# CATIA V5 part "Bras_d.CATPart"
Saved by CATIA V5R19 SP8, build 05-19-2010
Part number: Bras_d
Bounding box of the stored display mesh (mm): x -50 to 50, y -224.818 to 50, z -250 to 30
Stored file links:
  G:\EU_thinkMotion\CFAO_2010\MMS_groupe1\MMS_groupe1\OK\vduret\vduret\CATIA\Bras_d.CATPart
  G:\EU_thinkMotion\CFAO_2010\MMS_groupe1\MMS_groupe1\OK\vduret\vduret\CATIA\Axe_outil_g.CATPart
  G:\EU_thinkMotion\CFAO_2010\MMS_groupe1\MMS_groupe1\OK\vduret\vduret\CATIA\Axe.CATPart
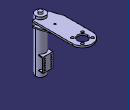
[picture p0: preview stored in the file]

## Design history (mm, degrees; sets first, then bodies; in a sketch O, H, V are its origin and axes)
Parameters
  Longueur_axe = 0 mm
External parameters (linked from other documents)
  External.Hauteur_bras = 200 mm
  External.Longueur_axe_couronne = 200 mm
Body1 (main body)
  Sketch1 on xy-plane, origin (0, 0, 0), H (1, 0, 0), V (0, 1, 0)
    arc A1 centre (0, 0) radius 50 from (50, 0) to (-50, 0) ccw
    point P1 (-50, 0)
    line L1 (-50, 0) -> (-50, -140)
    arc A2 centre (10, -200) radius 25 from (35, -200) to (-15, -200) ccw
    point P3 (10, -200)
    point P4 (50, 0)
    point P6 (35, -200)
    construction line L2 (-167.2305, -200) -> (322.7695, -200)
    circle A3 centre (0, 0) radius 25
    construction line L3 (-120, 0) -> (240, 0)
    point P9 (-120, 0)
    construction line L4 (0, -80) -> (0, 120)
    point P11 (0, -80)
    circle A4 centre (-25, 25) radius 7
    point P13 (-25, 25)
    circle A5 centre (25, 25) radius 7
    circle A6 centre (-25, -25) radius 7
    circle A7 centre (25, -25) radius 7
    line L5 (50, 0) -> (50, -200)
    point P17 (50, -200)
    line L6 (-50, -140) -> (-30, -200)
    point P18 (-30, -200)
    line L7 (-30, -200) -> (-15, -200)
    line L8 (35, -200) -> (50, -200)
    circle A8 centre (10, -127.5) radius 5
    point P20 (10, -127.5)
    axis line L9 (10, -200) -> (10, -128.2614)
    radius A1 = 50
    radius A2 = 25
    distance P3 H = 200 {= External.Hauteur_bras}
    length L1 = 140
    radius A3 = 25
    radius A4 = 7
    distance P13 L3 = 25
    distance P13 L4 = 25
    distance P3 L5 = 40
    length L7 = 15
    length L8 = 15
    radius A8 = 5
    distance P20 L2 = 72.5
    coincidence: P1 H, P4 H, P6 L2, P9 H, P11 V, P18 L2, P17 L8, P3 L2, P20 L9
    tangency: L1 A1, L5 A1
    horizontal: L2 H, L3 H, L7 H, L8 H
    vertical: L4 V, L9 V
    symmetry: A4 A5 L4, A4 A6 L3, A5 A7 L3
  Pad1: profile Sketch1, direction (0, 0, 1), length 8
  Plane1: type Offset, RefPlane xy-plane, Offset 18, reversed
  Sketch2 on Plane1, origin (0, 0, -18), H (1, 0, 0), V (0, 1, 0)
    arc A1 centre (10, -200) radius 25 from (35, -200) to (-15, -200) ccw
    reference projected arc E1 centre (10, -200) radius 25 from (35, -200) to (-15, -200) ccw from edge [face of Pad1 from Sketch1.A2 | end face of Pad1]
    line L1 (-15, -200) -> (-30, -200)
    point P3 (-30, -200)
    arc A2 centre (10, -127.5) radius 16 from (25.2387, -122.6235) to (-5.2387, -122.6235) ccw
    reference projected circle E2 centre (10, -127.5) radius 5 from edge [end face of Pad1 | face of Pad1 from Sketch1.A8]
    reference projected line E3 (-30, -200) -> (-15, -200) from edge [face of Pad1 from Sketch1.L7 | end face of Pad1]
    reference projected line E4 (-50, -140) -> (-30, -200) from edge [face of Pad1 from Sketch1.L6 | end face of Pad1]
    line L2 (35, -200) -> (50, -200)
    point P5 (35, -200)
    point P6 (50, -200)
    reference projected line E5 (35, -200) -> (50, -200) from edge [face of Pad1 from Sketch1.L8 | end face of Pad1]
    reference projected line E6 (50, -200) -> (50, 0) from edge [face of Pad1 from Sketch1.L5 | end face of Pad1]
    line L3 (50, -200) -> (25.2387, -122.6235)
    line L4 (-30, -200) -> (-5.2387, -122.6235)
    circle A3 centre (10, -127.5) radius 5
    reference projected circle E7 centre (10, -127.5) radius 5 from edge [end face of Pad1 | face of Pad1 from Sketch1.A8]
    reference projected circle E8 centre (10, -127.5) radius 5 from edge [end face of Pad1 | face of Pad1 from Sketch1.A8]
    radius A2 = 16
    coincidence: A1 E1, P3 E3, P3 E4, P5 L1, L2 E5, P6 E6, A3 E7
    horizontal: L1 H
    concentricity: A2 E2, A3 E8
    tangency: L3 A2, L4 A2
  Pad2: profile Sketch2, direction (0, 0, -1), length 6
  Sketch3 on xy-plane, origin (0, 0, 0), H (1, 0, 0), V (0, 1, 0)
    circle A1 centre (10, -200) radius 25
    reference projected arc E1 centre (10, -200) radius 25 from (35, -200) to (-15, -200) ccw from edge [face of Pad1 from Sketch1.A2 | end face of Pad1]
    coincidence: A1 E1
  Pad3: profile Sketch3, direction (0, 0, 1), length 20, opposite side length 240 {= External.Longueur_axe_couronne +40mm}
  Sketch4 on start face of Pad3, origin (0, 0, -240), H (1, 0, 0), V (0, -1, 0)
    circle A1 centre (10, 200) radius 10
    reference projected circle E1 centre (10, 200) radius 25 from edge [start face of Pad3 | face of Pad3 from Sketch3.A1]
    radius A1 = 10
    concentricity: A1 E1
  Pad4: profile Sketch4, direction (0, 0, -1), length 10
  Sketch5 on end face of Pad3, origin (0, 0, 20), H (1, 0, 0), V (0, 1, 0)
    circle A1 centre (10, -200) radius 10
    reference projected circle E1 centre (10, -200) radius 25 from edge [face of Pad3 from Sketch3.A1 | end face of Pad3]
    radius A1 = 10
    concentricity: A1 E1
  Pad5: profile Sketch5, direction (0, 0, 1), length 10
  Point1: type Center, Curve edge [start face of Pad3 | face of Pad3 from Sketch3.A1]
  Plane2: type OffsetPt, RefPlane yz-plane, RefPoint Point1
  Sketch6 on Plane2, origin (10, 0, 0), H (0, 1, 0), V (0, 0, 1)
    line L1 (-184, -140) -> (-162, -140)
    line L2 (-162, -140) -> (-162, -210)
    line L3 (-162, -210) -> (-184, -210)
    line L4 (-184, -210) -> (-184, -206)
    line L5 (-184, -206) -> (-166, -206)
    line L6 (-166, -206) -> (-166, -144)
    line L7 (-166, -144) -> (-184, -144)
    line L8 (-184, -144) -> (-184, -140)
    reference projected line E1 through (-200, 0) direction (0, 1) from axis of face of Pad3 from Sketch3.A1
    reference projected line E2 (-225, -240) -> (-175, -240) from edge [start face of Pad3 | face of Pad3 from Sketch3.A1]
    length L2 = 70
    distance L1 L7 = 4
    distance L5 L3 = 4
    distance L6 L2 = 4
    distance L8 E1 = 16
    length L1 = 22
    distance L3 E2 = 30
    horizontal: L1 H, L3 H, L5 H, L7 H
    vertical: L2 V, L4 V, L6 V, L8 V
    coincidence: L4 L8
  Pad6: profile Sketch6, direction (1, 0, 0), length 25, mirrored extent
  Sketch7 on face of Pad6 from Sketch6.L2, origin (0, -162, 0), H (-1, 0, 0), V (0, 0, 1)
    circle A1 centre (-26, -170) radius 3
    point P1 (-26, -170)
    construction line L1 (65, -380) -> (65, -460)
    circle A2 centre (-22.801, -391.0745) radius 0
    point P5 (-26, -150)
    circle A3 centre (-26, -150) radius 3
    point P6 (-27, -430)
    point P7 (-26, -160)
    circle A4 centre (-26, -160) radius 3
    construction line L2 (-26, -460) -> (-26, -370)
    reference projected line E1 (-35, -450) -> (-35, -380) from edge [face of Pad6 from Sketch6.L2 | end face of Pad6]
    reference projected line E2 (15, -450) -> (15, -380) from edge [start face of Pad6 | face of Pad6 from Sketch6.L2]
    construction line L3 (-10, -460) -> (-10, -380)
    reference projected line E3 (-35, -450) -> (-35, -380) from edge [face of Pad6 from Sketch6.L2 | end face of Pad6]
    axis line L4 (-51.764, -175) -> (28.236, -175)
    reference projected line E4 (15, -140) -> (-35, -140) from edge [face of Pad6 from Sketch6.L1 | face of Pad6 from Sketch6.L2]
    reference projected line E5 (15, -140) -> (-35, -140) from edge [face of Pad6 from Sketch6.L1 | face of Pad6 from Sketch6.L2]
    circle A5 centre (-26, -200) radius 3
    circle A6 centre (-26, -190) radius 3
    circle A7 centre (-26, -180) radius 3
    circle A8 centre (6, -150) radius 3
    circle A9 centre (6, -160) radius 3
    circle A10 centre (6, -170) radius 3
    circle A11 centre (6, -180) radius 3
    circle A12 centre (6, -190) radius 3
    circle A13 centre (6, -200) radius 3
    radius A1 = 3
    distance P5 P7 = 10
    distance P7 P1 = 10
    distance L3 E3 = 25
    distance L4 E4 = 35
    radius A3 = 3
    radius A4 = 3
    radius A1 = 3 (reference)
    distance P5 E5 = 10
    distance L2 L3 = 16
    vertical: L1 V, L2 V, L3 V
    coincidence: L2 P5, P7 L2, P1 L2
    symmetry: L1 E1 E2, A3 A5 L4, A4 A6 L4, A1 A7 L4, A3 A8 L3, A4 A9 L3, A1 A10 L3, A7 A11 L3, A6 A12 L3, A5 A13 L3
    horizontal: L4 H
  Pocket1: profile Sketch7, direction (0, -1, 0), through (limit type 6)
  Sketch8 on start face of Pad1, origin (0, 0, 0), H (1, 0, 0), V (0, -1, 0)
    circle A1 centre (10, 127.5) radius 5
    reference projected circle E1 centre (10, 127.5) radius 5 from edge [face of Pad1 from Sketch1.A8 | start face of Pad1]
    point P2 (0, 110)
    circle A2 centre (10, 127.5) radius 7.5
    radius A2 = 7.5
    coincidence: A1 E1
  Pad7: profile Sketch8, direction (0, 0, -1), length 7
  Sketch9 on start face of Pad2, origin (0, 0, -18), H (1, 0, 0), V (0, 1, 0)
    circle A1 centre (10, -127.5) radius 5
    circle A2 centre (10, -127.5) radius 7.5
    reference projected circle E1 centre (10, -127.5) radius 5 from edge [start face of Pad2 | face of Pad2 from Sketch2.A3]
    radius A2 = 7.5
    coincidence: A1 E1
  Pad8: profile Sketch9, direction (0, 0, 1), length 7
